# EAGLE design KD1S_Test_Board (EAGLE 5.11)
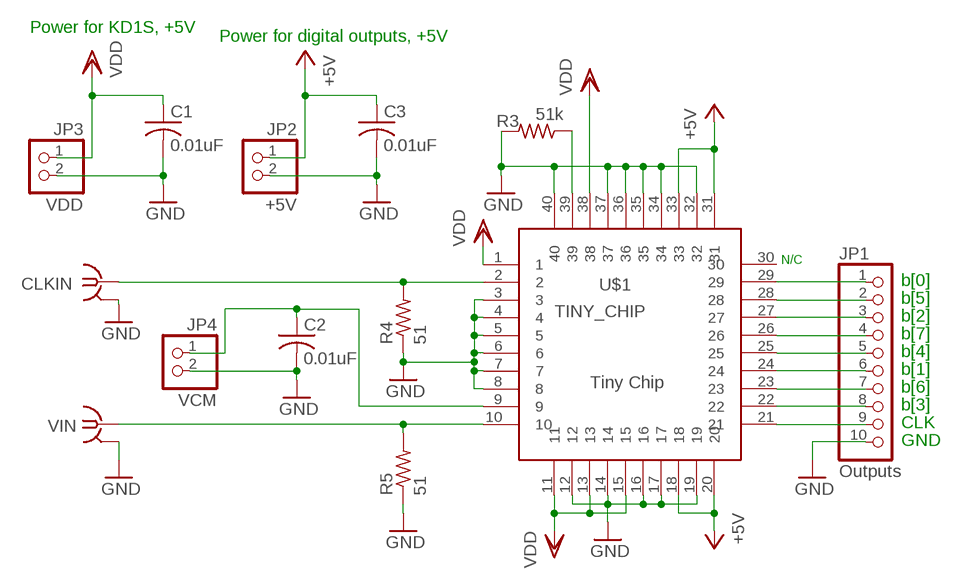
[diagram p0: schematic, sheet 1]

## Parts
C1  0.01uF  C-USC0805  [C0805]
C2  0.01uF  C-USC0805  [C0805]
C3  0.01uF  C-USC0805  [C0805]
CLKIN  SMA-142-0701-801/806  [J502-ND-142-0701-801/806]
JP1  Outputs  PINHD-1X10  [1X10]
JP2  +5V  PINHD-1X2  [1X02]
JP3  VDD  PINHD-1X2  [1X02]
JP4  VCM  PINHD-1X2  [1X02]
R3  51k  R-US_R0402  [R0402]
R4  51  R-US_R1210  [R1210]
R5  51  R-US_R1210  [R1210]
U$1  TINY_CHIP  [TINY_CHIP]
VIN  SMA-142-0701-801/806  [J502-ND-142-0701-801/806]

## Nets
+5V: C3.1 JP2.1 U$1.18 U$1.20 U$1.31 U$1.33
GND: C1.2 C2.2 C3.2 CLKIN.G@1(GND) JP1.10 JP2.2 JP3.2 JP4.2 R3.2 R4.1 R5.1 U$1.3 U$1.4 U$1.5 U$1.6 U$1.7 U$1.8 U$1.12 U$1.14 U$1.16 U$1.17 U$1.19 U$1.32 U$1.34 U$1.35 U$1.36 U$1.37 U$1.40 VIN.G@1(GND)
N$1: JP1.9 U$1.21
N$2: JP1.8 U$1.22
N$3: JP1.7 U$1.23
N$4: JP1.6 U$1.24
N$5: JP1.5 U$1.25
N$6: JP1.4 U$1.26
N$7: JP1.3 U$1.27
N$8: JP1.2 U$1.28
N$9: JP1.1 U$1.29
N$10: R3.1 U$1.39
N$11: R5.2 U$1.10 VIN.1
N$12: C2.1 JP4.1 U$1.9
N$21: CLKIN.1 R4.2 U$1.2
VDD: C1.1 JP3.1 U$1.1 U$1.11 U$1.13 U$1.15 U$1.38
Unconnected: U$1.30

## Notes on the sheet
- Power for KD1S, +5V
- Power for digital outputs, +5V
- N/C
- b[0]
- b[5]
- b[2]
- b[7]
- b[4]
- b[1]
- b[6]
- b[3]
- CLK
- GND

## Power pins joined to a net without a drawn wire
GND: CLKIN.G@2(GND) CLKIN.G@3(GND) CLKIN.G@4(GND) VIN.G@2(GND) VIN.G@3(GND) VIN.G@4(GND)

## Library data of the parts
C1-C3 = rcl:C-US: CAPACITOR, American symbol
CLKIN VIN = con-coax:SMA-: SMA 50 Ohm End Launch Jack Receptacle - Round Contact Johnson Components Source: www.johnsoncomponents.com .. J502-ND.pdf; MF: JOHNSON COMPONENTS; MPN: 142-0701-801; OC_FARNELL: 1608592; OC_NEWARK: 90F2624
JP1 = pinhead:PINHD-1X10: PIN HEADER
JP2-JP4 = pinhead:PINHD-1X2: PIN HEADER
R3-R5 = rcl:R-US_: RESISTOR, American symbol
U$1 = tiny_chip:TINY_CHIP: Tiny_Chip

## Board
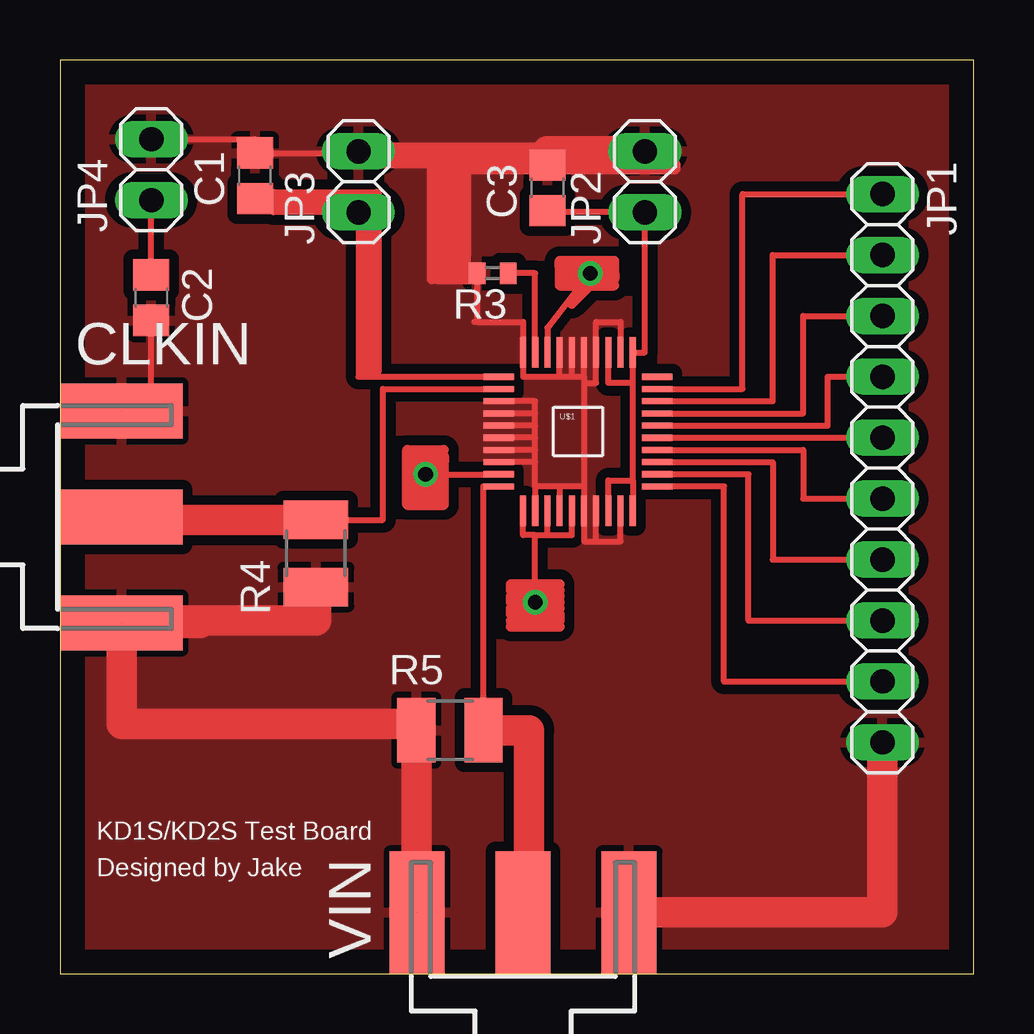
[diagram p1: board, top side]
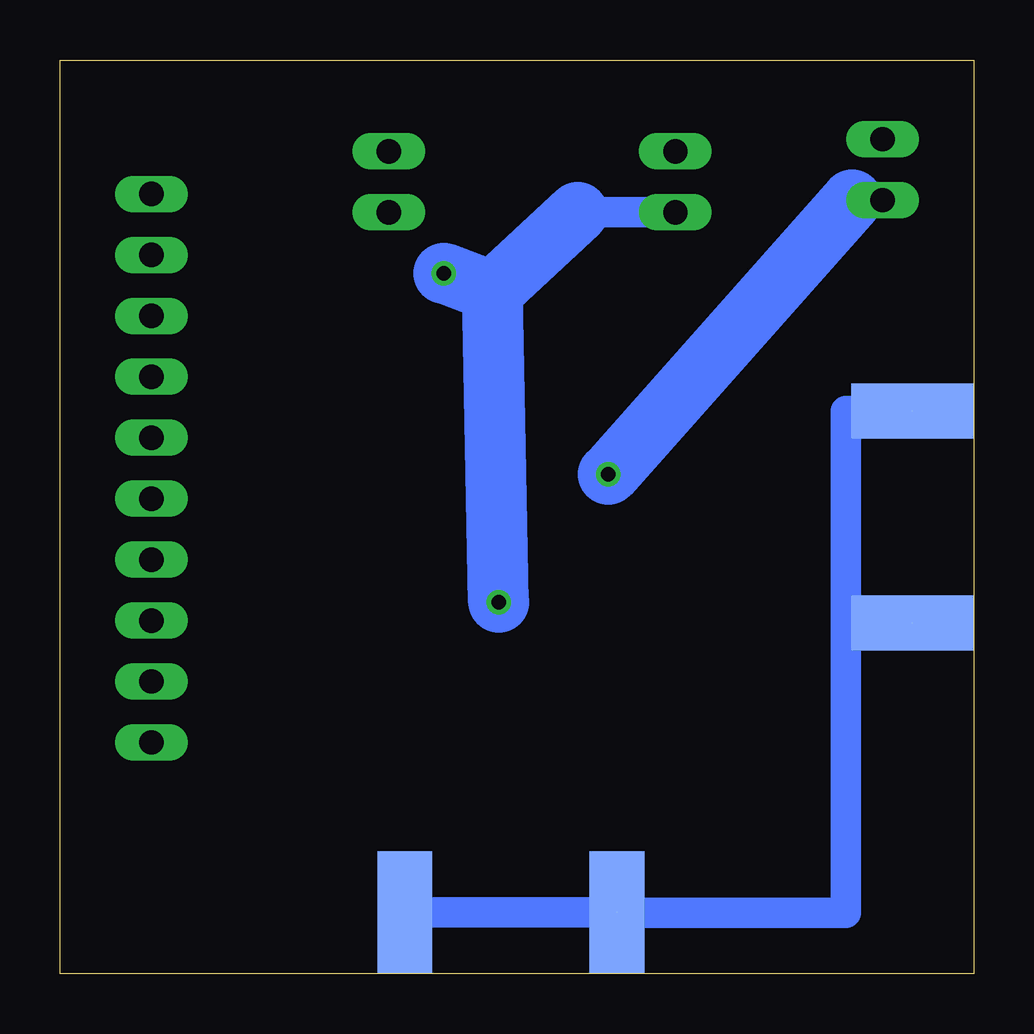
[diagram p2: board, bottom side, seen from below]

Size 38.1 x 38.1 mm. Coordinates in mm from the lower left corner, seen from the top.
Outline: 0,0 38.1,0 38.1,38.1 0,38.09 0,0
Copper layers (1*16): Top 0.035mm / dielectric 1.5mm / Bottom 0.035mm
Design rules "default": minimum track width 10mil, minimum drill 24mil, track to track 8mil, track to pad 8mil, pad to pad 8mil, via to via 8mil, smd to smd 8mil, copper to edge 40mil, drill to drill 8mil, minimum pad ring 10mil, minimum via ring 8mil, stop-mask expansion 4mil, vias tented up to drill 0mil, thermal gap 10mil

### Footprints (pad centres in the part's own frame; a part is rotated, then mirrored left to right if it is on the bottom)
C0805 = smd 1.3 x 1.5: 1 -0.95,0; 2 0.95,0
J502-ND-142-0701-801/806 = smd 5.08 x 2.286: 1 2.565,0; G@1 2.565,4.42; G@2 2.565,-4.42 | smd 5.08 x 2.286 bottom: G@3 2.565,4.42; G@4 2.565,-4.42
1X10 = drill 1.016 long: 1 -11.43,0; 2 -8.89,0; 3 -6.35,0; 4 -3.81,0; 5 -1.27,0; 6 1.27,0; 7 3.81,0; 8 6.35,0; 9 8.89,0; 10 11.43,0
1X02 = drill 1.016 long: 1 -1.27,0; 2 1.27,0
R0402 = smd 0.7 x 0.9: 1 -0.65,0; 2 0.65,0
R1210 = smd 1.6 x 2.7: 1 -1.4,0; 2 1.4,0
TINY_CHIP = smd 1.27 x 0.254: 1 -3.302,2.286; 2 -3.302,1.778; 3 -3.302,1.27; 4 -3.302,0.762; 5 -3.302,0.254; 6 -3.302,-0.254; 7 -3.302,-0.762; 8 -3.302,-1.27; 9 -3.302,-1.778; 10 -3.302,-2.286; 21 3.302,-2.286; 22 3.302,-1.778; 23 3.302,-1.27; 24 3.302,-0.762; 25 3.302,-0.254; 26 3.302,0.254; 27 3.302,0.762; 28 3.302,1.27; 29 3.302,1.778; 30 3.302,2.286 | smd 0.254 x 1.27: 11 -2.286,-3.302; 12 -1.778,-3.302; 13 -1.27,-3.302; 14 -0.762,-3.302; 15 -0.254,-3.302; 16 0.254,-3.302; 17 0.762,-3.302; 18 1.27,-3.302; 19 1.778,-3.302; 20 2.286,-3.302; 31 2.286,3.302; 32 1.778,3.302; 33 1.27,3.302; 34 0.762,3.302; 35 0.254,3.302; 36 -0.254,3.302; 37 -0.762,3.302; 38 -1.27,3.302; 39 -1.778,3.302; 40 -2.286,3.302

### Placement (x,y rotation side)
C1  8.13,33.27 90 top
C2  3.81,28.19 270 top
C3  20.32,32.77 90 top
CLKIN  0,19.05 0 top
JP1  34.29,21.08 270 top
JP2  24.38,33.02 90 top
JP3  12.45,33.02 90 top
JP4  3.81,33.53 90 top
R3  18.03,29.21 180 top
R4  10.67,17.53 90 top
R5  16.26,10.16 0 top
U$1  21.59,22.61 0 top
VIN  19.3,0 90 top

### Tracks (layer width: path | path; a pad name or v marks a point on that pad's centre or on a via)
+5V
  Top 0.254: 23.88,20.57 23.88,24.64 | 23.88,20.57 U$1.20 | 23.88,20.57 22.86,20.57 U$1.18 | 23.88,24.64 U$1.31 24.38,25.91 JP2.1 20.32,31.75 C3.1 | 23.88,24.64 22.86,24.64 U$1.33
GND  (3 unrouted)
  Top 0.254: U$1.19 23.37,18.03 22.35,18.03 | 22.35,18.03 U$1.17 | 22.35,18.03 21.84,18.03 U$1.16 21.84,20.32 | 21.84,24.64 21.84,20.32 | 21.84,24.89 21.84,24.64 | 21.84,24.64 22.35,24.64 U$1.34 22.35,27.18 23.37,27.18 U$1.32 | 20.83,20.32 U$1.14 | 21.84,20.32 20.83,20.32 | 19.81,20.32 U$1.12 | 20.83,20.32 19.81,20.32 | 19.81,21.34 U$1.8 | 19.81,20.32 19.81,21.34 | 21.84,24.89 U$1.35 | 21.34,24.89 21.84,24.89 | 21.34,24.89 U$1.36 | 20.83,24.89 21.34,24.89 | 19.81,21.84 U$1.7 | 19.81,21.34 19.81,21.84 | 19.81,22.35 U$1.6 | 19.81,21.84 19.81,22.35 | 19.81,22.86 U$1.5 | 19.81,22.35 19.81,22.86 | 19.81,23.37 U$1.4 | 19.81,22.86 19.81,23.37 | U$1.3 19.81,23.88 19.81,23.37 | 20.83,24.89 U$1.37 | 20.83,24.89 19.3,24.89 U$1.40 19.3,27.18 17.38,27.18 | 17.02,34.54 17.02,29.21 17.27,29.21 R3.2 17.38,27.18 | 17.02,34.54 20.32,34.54 20.32,34.29 | 17.38,27.18 17.27,27.18 | 17.02,34.54 12.45,34.54 JP3.2 12.45,34.22 C1.2 8.13,34.8 JP4.2 | CLKIN.G@1 3.81,23.47 C2.2
  Top 0.406: 17.27,29.21 16.76,29.21 | 16.76,29.21 16.76,34.29 | 16.76,34.29 19.81,34.29 19.81,34.04 16.51,34.04 | 16.26,34.04 13.46,34.04 13.46,34.29 16.76,34.29 | 16.76,29.21 16.76,28.96 16.51,28.96 16.51,34.04 | 16.51,34.04 16.26,34.04 | 16.26,34.04 16.26,28.96 16,28.96 16,33.78 | 16,33.78 15.75,33.78 | 15.75,33.78 15.49,33.78 | 15.75,33.78 15.75,33.53 | 15.75,33.53 15.75,28.96 | 15.75,28.96 17.02,28.96 | 15.75,28.96 15.49,28.96 15.49,33.53 | 15.49,33.78 15.49,33.53 | 15.49,33.78 13.21,33.78 | 16,33.78 25.65,33.78 25.65,33.53 15.75,33.53 | 15.75,33.53 15.49,33.53
  Top 1.27: R4.1 10.67,14.73 5.84,14.73 | 5.84,14.73 5.11,14.73 CLKIN.G@4 | CLKIN.G@4 5.84,14.63 5.84,14.73 | VIN.G@1 14.86,5.11 R5.1 14.73,10.16 14.73,10.41 2.56,10.41 CLKIN.G@4 | VIN.G@4 34.29,2.56 JP1.10 | JP2.2 20.32,34.29 C3.2
  Bottom 1.27: CLKIN.G@1 5.33,23.47 5.33,2.54 14.88,2.54 VIN.G@1 VIN.G@4
  pour Top (isolate 0.406): 0,38.1 38.1,38.1 38.1,0 0,0
N$1
  Top 0.254: U$1.21 27.69,20.32 27.69,12.19 JP1.9
N$2
  Top 0.254: U$1.22 28.7,20.83 28.7,14.73 JP1.8
N$3
  Top 0.254: U$1.23 29.72,21.34 29.72,17.27 JP1.7
N$4
  Top 0.254: U$1.24 30.99,21.84 30.99,19.81 JP1.6
N$5
  Top 0.254: U$1.25 JP1.5
N$6
  Top 0.254: U$1.26 32,22.86 32,24.89 JP1.4
N$7
  Top 0.254: U$1.27 30.99,23.37 30.99,27.43 JP1.3
N$8
  Top 0.254: U$1.28 29.72,23.88 29.72,29.97 JP1.2
N$9
  Top 0.254: U$1.29 28.45,24.38 28.45,32.51 JP1.1
N$10
  Top 0.254: U$1.39 19.81,29.21 R3.1
N$11
  Top 0.254: U$1.10 17.66,20.32 R5.2
  Top 1.27: VIN.1 19.56,5.11 19.56,10.16 R5.2
N$12  (via drill 0.61)
  Top 0.254: C2.1 JP4.1 | v15.24,20.83 15.75,20.83 U$1.9
  Top 0.406: 15.75,20.83 15.75,21.08 14.48,21.08 14.48,20.83 15.75,20.83 | 15.75,20.83 15.75,20.32 14.48,20.32 14.48,20.57 16,20.57
  Bottom 0.254: JP4.1 5.08,32.26
  Bottom 2.54: 5.08,32.26 v15.24,20.83
N$13
  Top 0.406: 16,19.81 16,20.07 | 16,19.81 14.48,19.81 14.48,20.07 16,20.07 | 16,19.81 16,19.56 14.48,19.56 14.48,21.59 | 14.48,21.59 16,21.59 16,21.34 | 16,20.07 16,21.34 | 16,21.34 14.73,21.34 14.48,21.59 | 14.48,21.59 14.48,21.84 16,21.84
N$21
  Top 0.254: R4.2 13.46,18.93 13.46,24.38 U$1.2
  Top 1.27: R4.2 5.11,18.93 CLKIN.1
VDD  (via drill 0.61)
  Top 0.254: C1.1 8.89,32.32 8.89,32.26 8.89,31.75 JP3.1 12.45,24.89 U$1.1 | U$1.15 21.34,18.29 20.32,18.29 | 20.32,18.29 U$1.13 | U$1.11 19.3,18.29 19.81,18.29 | 19.81,18.29 20.32,18.29 | v22.1,29.21 20.32,26.92 U$1.38 | v19.81,15.49 19.81,18.29
  Top 0.406: 20.83,14.48 18.8,14.48 18.8,14.73 20.57,14.73 20.57,15.49 20.83,15.75 | 23.11,29.21 v22.1,29.21 21.08,29.21 21.08,28.96 23.11,28.96 23.11,29.21 | 23.11,29.21 23.11,29.46 | 23.11,29.46 23.11,29.72 20.83,29.72 20.83,29.46 | 23.11,29.46 20.83,29.46 | 20.83,29.46 20.83,28.7 22.1,28.7 | 22.1,28.7 23.11,28.7 | 22.1,28.7 21.34,27.94 | 20.83,15.49 20.83,15.75 | 20.83,15.75 18.8,15.75 18.8,15.49 v19.81,15.49 20.83,15.49 | 20.83,15.49 20.83,15.24 18.8,15.24 18.8,14.99 20.83,14.99 20.83,14.73 | 20.83,15.75 20.83,16 18.8,16 18.8,16.26 20.83,16.26 | 9.14,32 12.7,32 12.7,25.15 12.95,25.15 12.95,32.26 8.89,32.26 8.89,32.51 13.21,32.51 13.21,25.15
  Bottom 0.406: 16.51,31.75 JP3.1
  Bottom 1.27: JP3.1 16.26,31.75
  Bottom 2.54: 20.07,28.45 16.51,31.75 | 20.07,28.45 v22.1,29.21 | v19.81,15.49 20.07,28.45

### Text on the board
tNames: KD1S/KD2S Test Board | Designed by Jake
